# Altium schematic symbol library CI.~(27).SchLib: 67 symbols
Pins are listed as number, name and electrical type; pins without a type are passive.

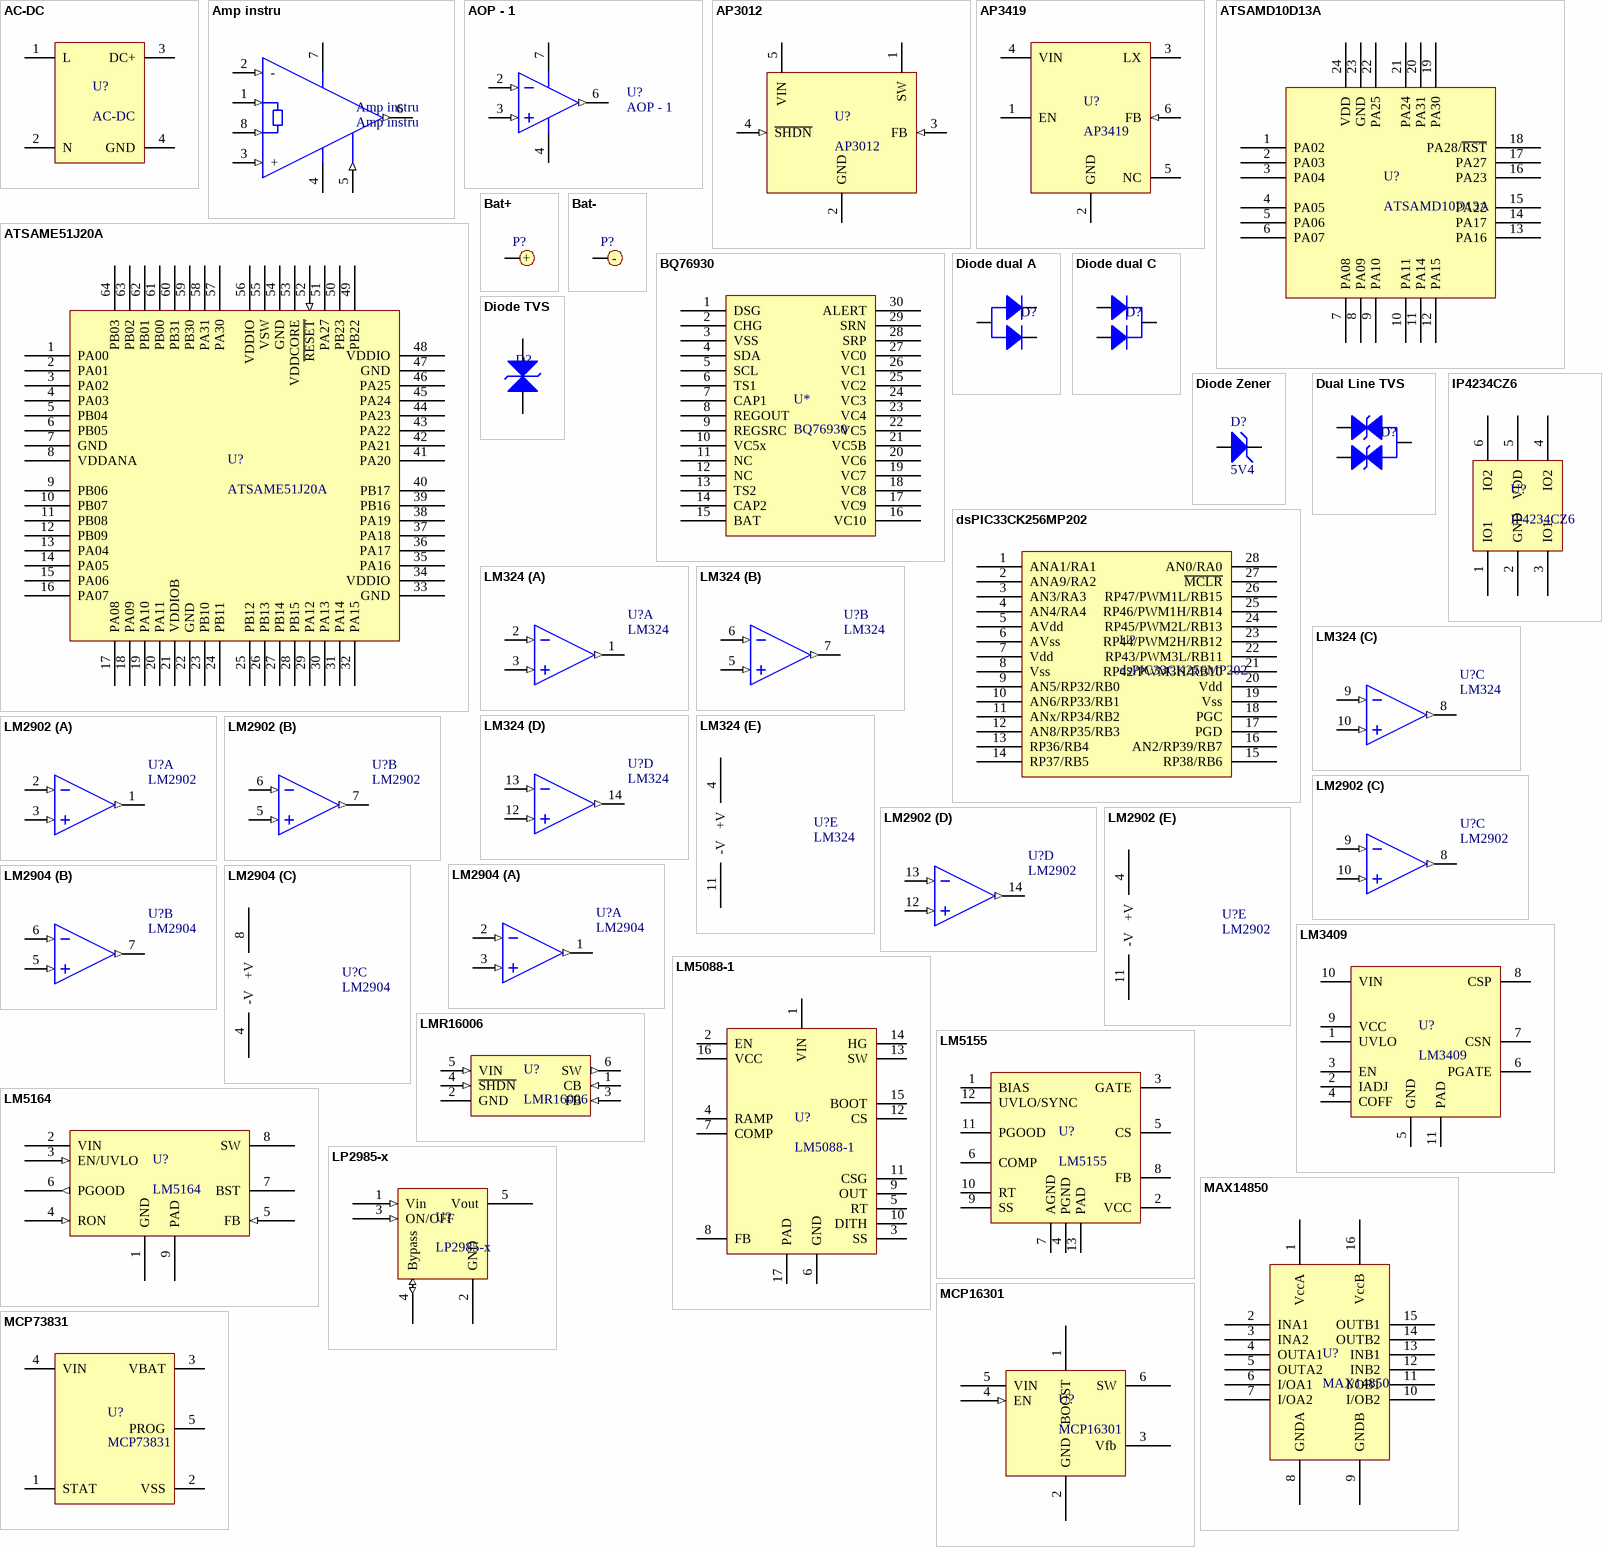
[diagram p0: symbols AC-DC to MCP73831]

## AC-DC
designator U?
footprint AC-DC 3W
footprint AC-DC 1W; pin to pad 1>4 2>3 3>2 4>1
pins: 1 L, 2 N, 3 DC+, 4 GND

## Amp instru
designator Amp instru
Instrument Amplifier
pins: 1 (in), 2 - (in), 3 + (in), 4 V- (power), 5 Ref (in), 6 OUT (out), 7 V+ (power), 8 (in)

## AOP - 1
designator U?
footprint SOIC-8 (8-Pin Plastic Narrow Body Small Outline Integrated Circuit 1.27 mm Pitch, IPC Medium Density)
pins: 2 IN- (in), 3 IN+ (in), 4 V- (power), 6 OUT (out), 7 V+ (power)

## AP3012
designator U?
1.5MHz boost DC-DC converter, current mode
footprint SOT-23-5 (SOT-23 5pins)
pins: 1 SW, 2 GND (power), 3 FB (in), 4 ~{SHDN} (in), 5 VIN (power)

## AP3419
designator U?
2A buck DC-DC converter
footprint TSOP2-6 (TSOP, 6-Leads, Body 2,90x1,60mm, Pitch 0,95mm, IPC Medium Density)
pins: 1 EN, 2 GND (power), 3 LX (power), 4 VIN (power), 5 NC (hiz), 6 FB (in)

## ATSAMD10D13A
designator U?
footprint SMSC QFN-24 4x4MM (QFN, 24-Leads, Body 4.1x4.1mm (max), Pitch 0.50mm, IPC Medium Density)
pins: 1 PA02, 2 PA03, 3 PA04, 4 PA05, 5 PA06, 6 PA07, 7 PA08, 8 PA09, 9 PA10, 10 PA11, 11 PA14, 12 PA15, 13 PA16, 14 PA17, 15 PA22, 16 PA23, 17 PA27, 18 PA28/~{RST}, 19 PA30, 20 PA31, 21 PA24, 22 PA25, 23 GND (power), 24 VDD (power)

## ATSAME51J20A
designator U?
footprint TQFP-64N (TSQFP, 64-Leads, Body 10,00x10,00mm, Pitch 0,50mm, IPC Medium Density)
pins: 1 PA00, 2 PA01, 3 PA02, 4 PA03, 5 PB04, 6 PB05, 7 GND (power), 8 VDDANA (power), 9 PB06, 10 PB07, 11 PB08, 12 PB09, 13 PA04, 14 PA05, 15 PA06, 16 PA07, 17 PA08, 18 PA09, 19 PA10, 20 PA11, 21 VDDIOB (power), 22 GND (power), 23 PB10, 24 PB11, 25 PB12, 26 PB13, 27 PB14, 28 PB15, 29 PA12, 30 PA13, 31 PA14, 32 PA15, 33 GND (power), 34 VDDIO (power), 35 PA16, 36 PA17, 37 PA18, 38 PA19, 39 PB16, 40 PB17, 41 PA20, 42 PA21, 43 PA22, 44 PA23, 45 PA24, 46 PA25, 47 GND (power), 48 VDDIO (power), 49 PB22, 50 PB23, 51 PA27, 52 ~{RESET} (in), 53 VDDCORE (power), 54 GND (power), 55 VSW (power), 56 VDDIO (power), 57 PA30, 58 PA31, 59 PB30, 60 PB31, 61 PB00, 62 PB01, 63 PB02, 64 PB03

## Bat+
designator P?  (value not drawn)
Battery contact +
footprint Keystone 2982 (Battery contact Keystone 2982)
pins: 1

## Bat-
designator P?  (value not drawn)
Battery contact -
footprint Keystone 2993 (Battery contact Keystone 2993)
pins: 1

## BQ76930
designator U*
footprint TSSOP-30
pins: 1 DSG, 2 CHG, 3 VSS, 4 SDA, 5 SCL, 6 TS1, 7 CAP1, 8 REGOUT, 9 REGSRC, 10 VC5x, 11 NC, 12 NC, 13 TS2, 14 CAP2, 15 BAT, 16 VC10, 17 VC9, 18 VC8, 19 VC7, 20 VC6, 21 VC5B, 22 VC5, 23 VC4, 24 VC3, 25 VC2, 26 VC1, 27 VC0, 28 SRP, 29 SRN, 30 ALERT

## Diode dual A
designator D?
Diode 2 common Anode
footprint DIODES SOT-23-3 (SOT23, 3-Leads, Body 2.90x2.40mm, Pitch 0.95mm, IPC Medium Density)
pins: 1 K1, 2 K2, 3 A

## Diode dual C
designator D?
Diode 2 common Cathode
footprint DIODES SOT-23-3 (SOT23, 3-Leads, Body 2.90x2.40mm, Pitch 0.95mm, IPC Medium Density)
pins: 1 A1, 2 A2, 3 K

## Diode TVS
designator D?  (value not drawn)
TVS diode
pins: A, K

## Diode Zener
designator D?, comment 5V4
Diode Zener
footprint DIODE-0.7 (Diode, Thru-Hole; 2 Leads; 0.7 in Pin Spacing)
simulation model ZENER (Diode)
signal-integrity model D Zener
pins: 1 A, 2 K

## dsPIC33CK256MP202
designator U?
footprint TI SSOP-28 DB (TSSOP, 28-Leads, Body 10.20x5.30mm, Pitch 0.65mm, IPC Medium Density)
pins: 1 ANA1/RA1, 2 ANA9/RA2, 3 AN3/RA3, 4 AN4/RA4, 5 AVdd (power), 6 AVss (power), 7 Vdd (power), 8 Vss (power), 9 AN5/RP32/RB0, 10 AN6/RP33/RB1, 11 ANx/RP34/RB2, 12 AN8/RP35/RB3, 13 RP36/RB4, 14 RP37/RB5, 15 RP38/RB6, 16 AN2/RP39/RB7, 17 PGD, 18 PGC, 19 Vss (power), 20 Vdd (power), 21 RP42/PWM3H/RB10, 22 RP43/PWM3L/RB11, 23 RP44/PWM2H/RB12, 24 RP45/PWM2L/RB13, 25 RP46/PWM1H/RB14, 26 RP47/PWM1L/RB15, 27 ~{MCLR}, 28 AN0/RA0

## Dual Line TVS
designator D?
Dual Line TVS
footprint DIODES SOT-23-3 (SOT23, 3-Leads, Body 2.90x2.40mm, Pitch 0.95mm, IPC Medium Density)
pins: 1, 2, 3

## IP4234CZ6
designator U?
Single USB 2.0 ESD protection to IEC 61000-4-2 level 4
footprint VISHAY TSOP-6 MO-193C (SOT23, 6-Leads, Body 3.03x2.84mm, Pitch 0.95mm, IPC Medium Density)
pins: 1 IO1, 2 GND (power), 3 IO1, 4 IO2, 5 VDD (power), 6 IO2

## LM324
designator U?
ow power quad operational amplifiers
footprint SOIC-14 (14-Pin Plastic Narrow Body Small Outline Integrated Circuit 1.27 mm Pitch, IPC Medium Density)
part A pins: 1 OUT (out), 2 IN- (in), 3 IN+ (in)
part B pins: 5 IN+ (in), 6 IN- (in), 7 OUT (out)
part C pins: 8 OUT (out), 9 IN- (in), 10 IN+ (in)
part D pins: 12 IN+ (in), 13 IN- (in), 14 OUT (out)
part E pins: 4 +V (power), 11 -V (power)

## LM2902
designator U?
Low-power quad operational amplifiers
footprint Atmel SO-14 14S1 (SOIC, 14-Leads, Body 8.65x3.90mm, Pitch 1.27mm, IPC Medium Density)
part A pins: 1 OUT (out), 2 IN- (in), 3 IN+ (in)
part B pins: 5 IN+ (in), 6 IN- (in), 7 OUT (out)
part C pins: 8 OUT (out), 9 IN- (in), 10 IN+ (in)
part D pins: 12 IN+ (in), 13 IN- (in), 14 OUT (out)
part E pins: 4 +V (power), 11 -V (power)

## LM2904
designator U?
Low-power dual operational amplifiers
footprint DIODES SO-8 (SOIC, 8-Leads, Body 4.90x3.90mm, Pitch 1.27mm, IPC Medium Density)
part A pins: 1 OUT (out), 2 IN- (in), 3 IN+ (in)
part B pins: 5 IN+ (in), 6 IN- (in), 7 OUT (out)
part C pins: 4 -V (power), 8 +V (power)

## LM3409
designator U?
P-FET Buck Controller for High-Power LED Drivers
footprint TI MSOP-10 DGQ (TSSOP, 10-Leads, Body 3x3mm, Pitch 0.5mm, Thermal Pad 1.88x1.57mm, IPC Medium Density)
pins: 1 UVLO, 2 IADJ (power), 3 EN, 4 COFF, 5 GND (power), 6 PGATE, 7 CSN, 8 CSP, 9 VCC, 10 VIN (power), 11 PAD (power)

## LM5088-1
designator U?
Wide Input Range Non-Synchronous Buck Controller
footprint TI MSOP-10 DGQ (TSSOP, 10-Leads, Body 3x3mm, Pitch 0.5mm, Thermal Pad 1.88x1.57mm, IPC Medium Density)
pins: 1 VIN (power), 2 EN, 3 SS, 4 RAMP, 5 RT, 6 GND (power), 7 COMP, 8 FB, 9 OUT, 10 DITH, 11 CSG, 12 CS, 13 SW, 14 HG, 15 BOOT, 16 VCC (power), 17 PAD (power)

## LM5155
designator U?
2.2-MHz Wide Input Nonsynchronous Boost, SEPIC, Flyback Controller
footprint TI MSOP-10 DGQ (TSSOP, 10-Leads, Body 3x3mm, Pitch 0.5mm, Thermal Pad 1.88x1.57mm, IPC Medium Density)
pins: 1 BIAS, 2 VCC (power), 3 GATE, 4 PGND, 5 CS, 6 COMP, 7 AGND (power), 8 FB, 9 SS, 10 RT, 11 PGOOD, 12 UVLO/SYNC, 13 PAD (power)

## LM5164
designator U?
100-V Input, 1-A synchronous buck DC/DC converter with ultra-low IQ
footprint R-PDSO-G8 (SOIC, 8-Leads, Body 4,90x3,90mm, Pitch 1,27mm, Thermal Pad 3,10x2,40mm, IPC Medium Density)
pins: 1 GND (power), 2 VIN (power), 3 EN/UVLO (in), 4 RON (in), 5 FB (in), 6 PGOOD (out), 7 BST (power), 8 SW (power), 9 PAD (power)

## LMR16006
designator U?
4 to 60V in, 0.5V out buck converter
footprint DPSO-6
pins: 1 CB (in), 2 GND (power), 3 FB (in), 4 ~{SHDN} (in), 5 VIN (in), 6 SW (out)

## LP2985-x
designator U?
150mA, Low-Noise, 350mVdrop max, LDO voltage regulator
footprint SOT-23-5 (SOT-23 5pins)
pins: 1 Vin (in), 2 GND (power), 3 ON/OFF (in), 4 Bypass (io), 5 Vout (power)

## MAX14850
designator U?
Six-Channel Digital Isolator
footprint SI LABS SOIC-16 WIDE (SOIC, 16-Leads, Body 10.30x7.50mm, Pitch 1.27mm, IPC Medium Density)
pins: 1 VccA (power), 2 INA1, 3 INA2, 4 OUTA1, 5 OUTA2, 6 I/OA1, 7 I/OA2, 8 GNDA (power), 9 GNDB (power), 10 I/OB2, 11 I/OB1, 12 INB2, 13 INB1, 14 OUTB2, 15 OUTB1, 16 VccB (power)

## MCP16301
designator U?
High-Voltage Input Integrated Switch Step-Down Regulator
footprint TI SOT-23-6 DDC (SOT23, 6-Leads, Body 2.90x2.80mm, Pitch 0.95mm, IPC Medium Density)
pins: 1 BOOST, 2 GND (power), 3 Vfb, 4 EN (in), 5 VIN (power), 6 SW

## MCP73831
designator U?
Miniature Single-Cell, Fully Integrated Li-Ion,Li-Polymer Charge Management Controllers
footprint MICROCHIP SOT-23-5 OT (SOT23, 5-Leads, Body 2.90x2.70mm, Pitch 0.95mm, IPC Medium Density)
pins: 1 STAT, 2 VSS (power), 3 VBAT (power), 4 VIN (power), 5 PROG

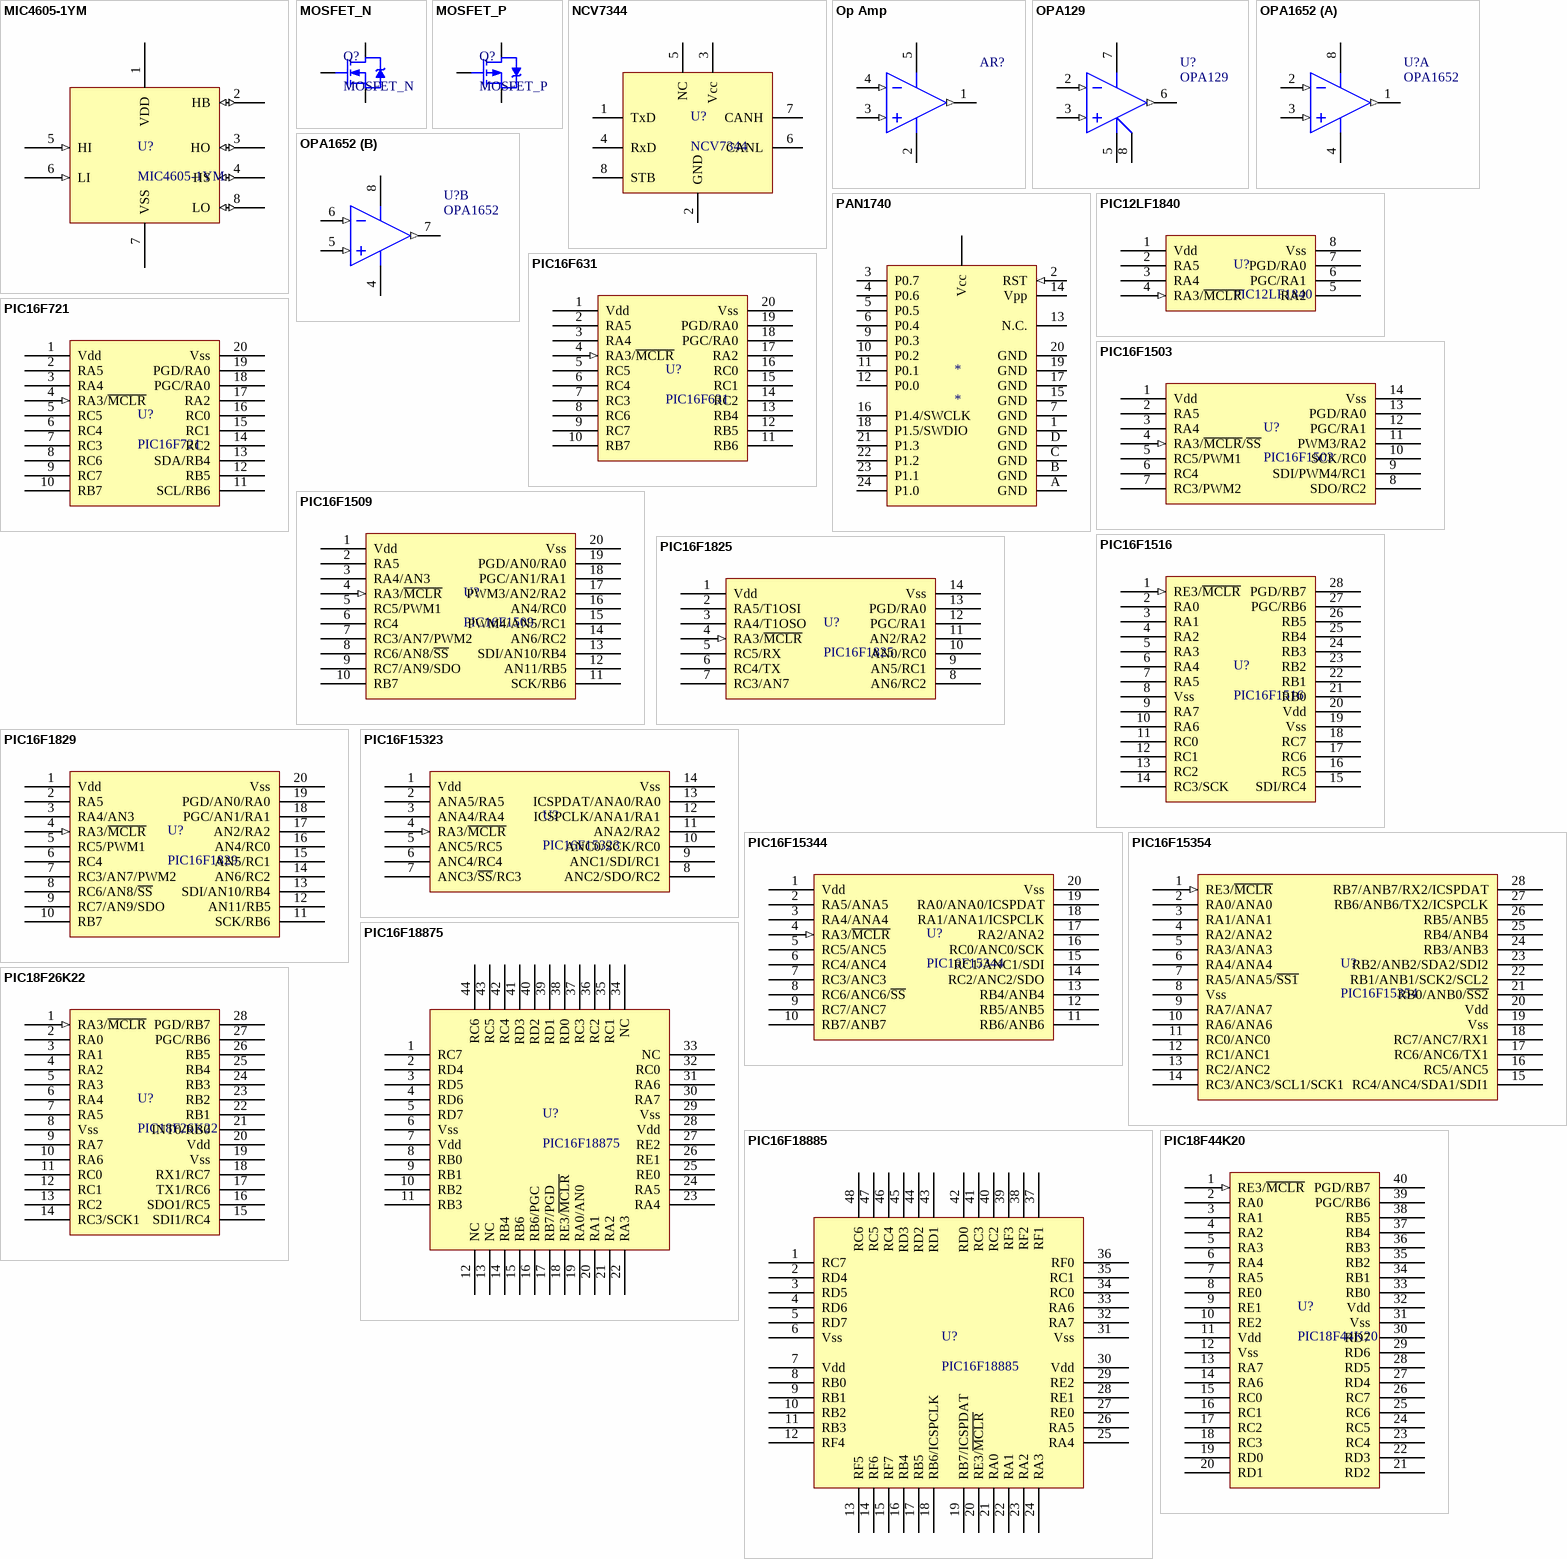
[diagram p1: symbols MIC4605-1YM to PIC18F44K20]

## MIC4605-1YM
designator U?
85V Half-Bridge MOSFET Driver with Adaptive Dead Time  and Shoot-Through Protection
footprint SOIC-8 (8-Pin Plastic Narrow Body Small Outline Integrated Circuit 1.27 mm Pitch, IPC Medium Density)
pins: 1 VDD (power), 2 HB (io), 3 HO (io), 4 HS (io), 5 HI (in), 6 LI (in), 7 VSS (power), 8 LO (io)

## MOSFET_N
designator Q?
pins: 1 G, 2 S, 3 D

## MOSFET_P
designator Q?
pins: 1 G, 2 S, 3 D

## NCV7344
designator U?
High Speed Low PowerCAN, CAN FD Transceiver
footprint ON SEMI SO-8 (SOIC, 8-Leads, Body 4.90x3.90mm, Pitch 1.27mm, IPC Medium Density)
pins: 1 TxD, 2 GND (power), 3 Vcc (power), 4 RxD, 5 NC (power), 6 CANL, 7 CANH, 8 STB

## Op Amp
designator AR?
FET Operational Amplifier
footprint H-08A (Can; 8 Leads; Pin Circle Dia. 5.08 mm; Lead Dia. 0.53 mm (max))
simulation model AD645A (Spice Subcircuit)
pins: 1 OUT (out), 2 V- (power), 3 IN+ (in), 4 IN- (in), 5 V+ (power)

## OPA129
designator U?
FET Operational Amplifier
footprint H-08A (Can; 8 Leads; Pin Circle Dia. 5.08 mm; Lead Dia. 0.53 mm (max))
simulation model AD645A (Spice Subcircuit)
pins: 2 IN- (in), 3 IN+ (in), 5 V- (power), 6 OUT (out), 7 V+ (power), 8 V- (power)

## OPA1652
designator U?
Low Noise and Distortion, General-Purpose, FET-Input Audio Op Amps
footprint SOIC-8 (8-Pin Plastic Narrow Body Small Outline Integrated Circuit 1.27 mm Pitch, IPC Medium Density)
pins on every part: 4 V- (power), 8 V+ (power)
part A pins: 1 OUT (out), 2 IN- (in), 3 IN+ (in)
part B pins: 5 IN+ (in), 6 IN- (in), 7 OUT (out)

## PAN1740
designator *
pins: 1 GND (power), 2 RST (in), 3 P0.7, 4 P0.6, 5 P0.5, 6 P0.4, 7 GND (power), 8 Vcc (power), 9 P0.3, 10 P0.2, 11 P0.1, 12 P0.0, 13 N.C., 14 Vpp (power), 15 GND (power), 16 P1.4/SWCLK, 17 GND (power), 18 P1.5/SWDIO, 19 GND (power), 20 GND (power), 21 P1.3, 22 P1.2, 23 P1.1, 24 P1.0, A GND (power), B GND (power), C GND (power), D GND (power)

## PIC12LF1840
designator U?
pins: 1 Vdd (power), 2 RA5, 3 RA4, 4 RA3/~{MCLR} (in), 5 RA2, 6 PGC/RA1, 7 PGD/RA0, 8 Vss (power)

## PIC16F631
designator U?
pins: 1 Vdd (power), 2 RA5, 3 RA4, 4 RA3/~{MCLR} (in), 5 RC5, 6 RC4, 7 RC3, 8 RC6, 9 RC7, 10 RB7, 11 RB6, 12 RB5, 13 RB4, 14 RC2, 15 RC1, 16 RC0, 17 RA2, 18 PGC/RA0, 19 PGD/RA0, 20 Vss (power)

## PIC16F721
designator U?
pins: 1 Vdd (power), 2 RA5, 3 RA4, 4 RA3/~{MCLR} (in), 5 RC5, 6 RC4, 7 RC3, 8 RC6, 9 RC7, 10 RB7, 11 SCL/RB6, 12 RB5, 13 SDA/RB4, 14 RC2, 15 RC1, 16 RC0, 17 RA2, 18 PGC/RA0, 19 PGD/RA0, 20 Vss (power)

## PIC16F1503
designator U?
pins: 1 Vdd (power), 2 RA5, 3 RA4, 4 RA3/~{MCLR}/~{SS} (in), 5 RC5/PWM1, 6 RC4, 7 RC3/PWM2, 8 SDO/RC2, 9 SDI/PWM4/RC1, 10 SCK/RC0, 11 PWM3/RA2, 12 PGC/RA1, 13 PGD/RA0, 14 Vss (power)

## PIC16F1509
designator U?
pins: 1 Vdd (power), 2 RA5, 3 RA4/AN3, 4 RA3/~{MCLR} (in), 5 RC5/PWM1, 6 RC4, 7 RC3/AN7/PWM2, 8 RC6/AN8/~{SS}, 9 RC7/AN9/SDO, 10 RB7, 11 SCK/RB6, 12 AN11/RB5, 13 SDI/AN10/RB4, 14 AN6/RC2, 15 PWM4/AN5/RC1, 16 AN4/RC0, 17 PWM3/AN2/RA2, 18 PGC/AN1/RA1, 19 PGD/AN0/RA0, 20 Vss (power)

## PIC16F1516
designator U?
pins: 1 RE3/~{MCLR} (in), 2 RA0, 3 RA1, 4 RA2, 5 RA3, 6 RA4, 7 RA5, 8 Vss (power), 9 RA7, 10 RA6, 11 RC0, 12 RC1, 13 RC2, 14 RC3/SCK, 15 SDI/RC4, 16 RC5, 17 RC6, 18 RC7, 19 Vss (power), 20 Vdd (power), 21 RB0, 22 RB1, 23 RB2, 24 RB3, 25 RB4, 26 RB5, 27 PGC/RB6, 28 PGD/RB7

## PIC16F1825
designator U?
footprint TSSOP-14
footprint SOIC-14 (14-Pin Plastic Narrow Body Small Outline Integrated Circuit 1.27 mm Pitch, IPC Medium Density)
pins: 1 Vdd (power), 2 RA5/T1OSI, 3 RA4/T1OSO, 4 RA3/~{MCLR} (in), 5 RC5/RX, 6 RC4/TX, 7 RC3/AN7, 8 AN6/RC2, 9 AN5/RC1, 10 AN0/RC0, 11 AN2/RA2, 12 PGC/RA1, 13 PGD/RA0, 14 Vss (power)

## PIC16F1829
designator U?
pins: 1 Vdd (power), 2 RA5, 3 RA4/AN3, 4 RA3/~{MCLR} (in), 5 RC5/PWM1, 6 RC4, 7 RC3/AN7/PWM2, 8 RC6/AN8/~{SS}, 9 RC7/AN9/SDO, 10 RB7, 11 SCK/RB6, 12 AN11/RB5, 13 SDI/AN10/RB4, 14 AN6/RC2, 15 AN5/RC1, 16 AN4/RC0, 17 AN2/RA2, 18 PGC/AN1/RA1, 19 PGD/AN0/RA0, 20 Vss (power)

## PIC16F15323
designator U?
footprint MICROCHIP TSSOP-14 4.4MM BODY (TSSOP, 14-Leads, Body 5.00x4.40mm, Pitch 0.65mm, IPC Medium Density)
pins: 1 Vdd (power), 2 ANA5/RA5, 3 ANA4/RA4, 4 RA3/~{MCLR} (in), 5 ANC5/RC5, 6 ANC4/RC4, 7 ANC3/~{SS}/RC3, 8 ANC2/SDO/RC2, 9 ANC1/SDI/RC1, 10 ANC0/SCK/RC0, 11 ANA2/RA2, 12 ICSPCLK/ANA1/RA1, 13 ICSPDAT/ANA0/RA0, 14 Vss (power)

## PIC16F15344
designator U?
footprint MICROCHIP TSSOP-20 4.4MM BODY (TSSOP, 20-Leads, Body 6.50x4.40mm, Pitch 0.65mm, IPC Medium Density)
pins: 1 Vdd (power), 2 RA5/ANA5, 3 RA4/ANA4, 4 RA3/~{MCLR} (in), 5 RC5/ANC5, 6 RC4/ANC4, 7 RC3/ANC3, 8 RC6/ANC6/~{SS}, 9 RC7/ANC7, 10 RB7/ANB7, 11 RB6/ANB6, 12 RB5/ANB5, 13 RB4/ANB4, 14 RC2/ANC2/SDO (power), 15 RC1/ANC1/SDI, 16 RC0/ANC0/SCK, 17 RA2/ANA2, 18 RA1/ANA1/ICSPCLK, 19 RA0/ANA0/ICSPDAT, 20 Vss

## PIC16F15354
designator U?
footprint SSOP_28
pins: 1 RE3/~{MCLR} (in), 2 RA0/ANA0, 3 RA1/ANA1, 4 RA2/ANA2, 5 RA3/ANA3, 6 RA4/ANA4, 7 RA5/ANA5/~{SS1}, 8 Vss (power), 9 RA7/ANA7, 10 RA6/ANA6, 11 RC0/ANC0, 12 RC1/ANC1, 13 RC2/ANC2, 14 RC3/ANC3/SCL1/SCK1, 15 RC4/ANC4/SDA1/SDI1, 16 RC5/ANC5, 17 RC6/ANC6/TX1, 18 RC7/ANC7/RX1, 19 Vss (power), 20 Vdd (power), 21 RB0/ANB0/~{SS2}, 22 RB1/ANB1/SCK2/SCL2, 23 RB2/ANB2/SDA2/SDI2, 24 RB3/ANB3, 25 RB4/ANB4, 26 RB5/ANB5, 27 RB6/ANB6/TX2/ICSPCLK, 28 RB7/ANB7/RX2/ICSPDAT

## PIC16F18875
designator U?
pins: 1 RC7, 2 RD4, 3 RD5, 4 RD6, 5 RD7, 6 Vss (power), 7 Vdd (power), 8 RB0, 9 RB1, 10 RB2, 11 RB3, 12 NC, 13 NC, 14 RB4, 15 RB6, 16 RB6/PGC, 17 RB7/PGD, 18 RE3/~{MCLR}, 19 RA0/AN0, 20 RA1, 21 RA2, 22 RA3, 23 RA4, 24 RA5, 25 RE0, 26 RE1, 27 RE2, 28 Vdd (power), 29 Vss (power), 30 RA7, 31 RA6, 32 RC0, 33 NC, 34 NC, 35 RC1, 36 RC2, 37 RC3, 38 RD0, 39 RD1, 40 RD2, 41 RD3, 42 RC4, 43 RC5, 44 RC6

## PIC16F18885
designator U?
footprint TQFP-48N (TSQFP, 48-Leads, Body 7,00x7,00mm, Pitch 0,50mm, IPC Medium Density)
pins: 1 RC7, 2 RD4, 3 RD5, 4 RD6, 5 RD7, 6 Vss (power), 7 Vdd (power), 8 RB0, 9 RB1, 10 RB2, 11 RB3, 12 RF4, 13 RF5, 14 RF6, 15 RF7, 16 RB4, 17 RB5, 18 RB6/ICSPCLK, 19 RB7/ICSPDAT, 20 RE3/~{MCLR}, 21 RA0, 22 RA1, 23 RA2, 24 RA3, 25 RA4, 26 RA5, 27 RE0, 28 RE1, 29 RE2, 30 Vdd (power), 31 Vss (power), 32 RA7, 33 RA6, 34 RC0, 35 RC1, 36 RF0, 37 RF1, 38 RF2, 39 RF3, 40 RC2, 41 RC3, 42 RD0, 43 RD1, 44 RD2, 45 RD3, 46 RC4, 47 RC5, 48 RC6

## PIC18F26K22
designator U?
pins: 1 RA3/~{MCLR} (in), 2 RA0, 3 RA1, 4 RA2, 5 RA3, 6 RA4, 7 RA5, 8 Vss (power), 9 RA7, 10 RA6, 11 RC0, 12 RC1, 13 RC2, 14 RC3/SCK1, 15 SDI1/RC4, 16 SDO1/RC5, 17 TX1/RC6, 18 RX1/RC7, 19 Vss (power), 20 Vdd (power), 21 INT0/RB0, 22 RB1, 23 RB2, 24 RB3, 25 RB4, 26 RB5, 27 PGC/RB6, 28 PGD/RB7

## PIC18F44K20
designator U?
pins: 1 RE3/~{MCLR} (in), 2 RA0, 3 RA1, 4 RA2, 5 RA3, 6 RA4, 7 RA5, 8 RE0, 9 RE1, 10 RE2, 11 Vdd (power), 12 Vss (power), 13 RA7, 14 RA6, 15 RC0, 16 RC1, 17 RC2, 18 RC3, 19 RD0, 20 RD1, 21 RD2, 22 RD3, 23 RC4, 24 RC5, 25 RC6, 26 RC7, 27 RD4, 28 RD5, 29 RD6, 30 RD7, 31 Vss (power), 32 Vdd (power), 33 RB0, 34 RB1, 35 RB2, 36 RB3, 37 RB4, 38 RB5, 39 PGC/RB6, 40 PGD/RB7

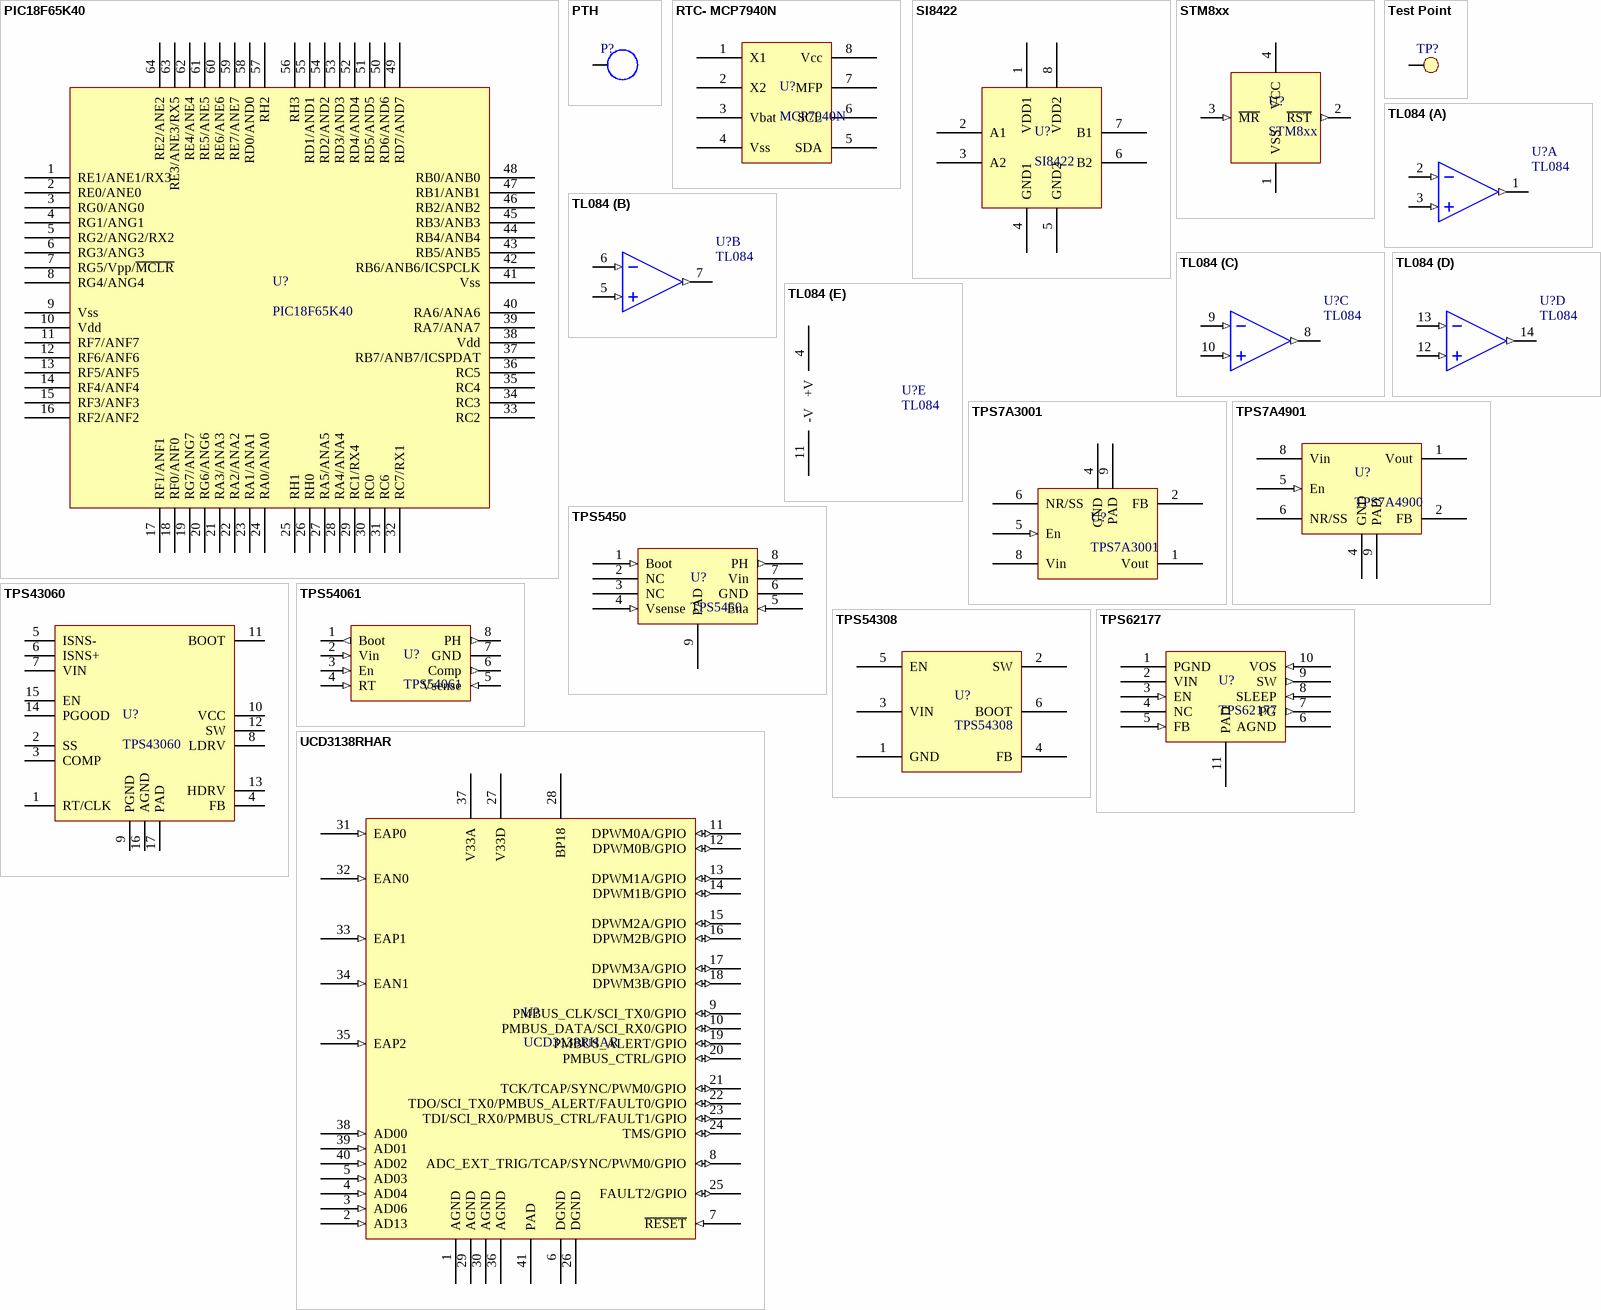
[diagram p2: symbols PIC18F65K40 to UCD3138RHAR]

## PIC18F65K40
designator U?
64-Pin, Low-Power, High-Performance Microcontrollers
footprint LQFP64 (LQFP, 64-Leads, Body 10,00x10,00mm, Pitch 0,50mm, IPC Medium Density)
pins: 1 RE1/ANE1/RX3, 2 RE0/ANE0, 3 RG0/ANG0, 4 RG1/ANG1, 5 RG2/ANG2/RX2, 6 RG3/ANG3, 7 RG5/Vpp/~{MCLR}, 8 RG4/ANG4, 9 Vss, 10 Vdd, 11 RF7/ANF7, 12 RF6/ANF6, 13 RF5/ANF5, 14 RF4/ANF4, 15 RF3/ANF3, 16 RF2/ANF2, 17 RF1/ANF1, 18 RF0/ANF0, 19 RG7/ANG7, 20 RG6/ANG6, 21 RA3/ANA3, 22 RA2/ANA2, 23 RA1/ANA1, 24 RA0/ANA0, 25 RH1, 26 RH0, 27 RA5/ANA5, 28 RA4/ANA4, 29 RC1/RX4, 30 RC0, 31 RC6, 32 RC7/RX1, 33 RC2, 34 RC3, 35 RC4, 36 RC5, 37 RB7/ANB7/ICSPDAT, 38 Vdd, 39 RA7/ANA7, 40 RA6/ANA6, 41 Vss, 42 RB6/ANB6/ICSPCLK, 43 RB5/ANB5, 44 RB4/ANB4, 45 RB3/ANB3, 46 RB2/ANB2, 47 RB1/ANB1, 48 RB0/ANB0, 49 RD7/AND7, 50 RD6/AND6, 51 RD5/AND5, 52 RD4/AND4, 53 RD3/AND3, 54 RD2/AND2, 55 RD1/AND1, 56 RH3, 57 RH2, 58 RD0/AND0, 59 RE7/ANE7, 60 RE6/ANE6, 61 RE5/ANE5, 62 RE4/ANE4, 63 RE3/ANE3/RX5, 64 RE2/ANE2

## PTH
designator P?  (value not drawn)
Plated Trough Hole for screew
footprint HOLE_4 (Hole for M4 screw)
pins: 1

## RTC- MCP7940N
designator U?, comment MCP7940N
pins: 1 X1, 2 X2, 3 Vbat, 4 Vss, 5 SDA, 6 SCL, 7 MFP, 8 Vcc

## SI8422
designator U?
Low-Power, Dual-Channel Digital Isolators
footprint ANALOG SO-8 R-8 (SOIC, 8-Leads, Body 4.90x3.90mm, Pitch 1.27mm, IPC Medium Density)
pins: 1 VDD1 (power), 2 A1, 3 A2, 4 GND1 (power), 5 GND2 (power), 6 B2, 7 B1, 8 VDD2 (power)

## STM8xx
designator U?
Voltage monitor
footprint SOT143-4
pins: 1 VSS (power), 2 ~{RST} (out), 3 ~{MR} (in), 4 VCC (power)

## Test Point
designator TP?  (value not drawn)
footprint Test Point
pins: 1

## TL084
designator U?
Quad operational amplifiers, 36V
footprint TSSOP-14
part A pins: 1 OUT (out), 2 IN- (in), 3 IN+ (in)
part B pins: 5 IN+ (in), 6 IN- (in), 7 OUT (out)
part C pins: 8 OUT (out), 9 IN- (in), 10 IN+ (in)
part D pins: 12 IN+ (in), 13 IN- (in), 14 OUT (out)
part E pins: 4 +V (power), 11 -V (power)

## TPS7A3001
designator U?
Ultra low noise positive adjustable LDO
footprint DGN8_PAD (MSOP-PowerPAD; 8 Leads; Pitch 0.65 mm)
simulation model TPS7A3001
pins: 1 Vout (power), 2 FB, 4 GND (power), 5 En (in), 6 NR/SS, 8 Vin (power), 9 PAD (power)

## TPS7A4901
designator U?, comment TPS7A4900
Ultra low noise positive adjustable LDO
footprint DGN8_PAD (MSOP-PowerPAD; 8 Leads; Pitch 0.65 mm)
simulation model TPS7A4901
pins: 1 Vout (power), 2 FB, 4 GND (power), 5 En (in), 6 NR/SS, 8 Vin (power), 9 PAD (power)

## TPS5450
designator U?
pins: 1 Boot (in), 2 NC (hiz), 3 NC (hiz), 4 Vsense (in), 5 Ena (in), 6 GND (power), 7 Vin (power), 8 PH (out), 9 PAD (power)

## TPS43060
designator U?
Low Quiescent Current Synchronous Boost  DC-DC Controller With Wide VIN Range
footprint TI WQFN-16 RGH (QFN, 16-Leads, Body 4.00x4.00mm, Pitch 0.50mm, Thermal Pad 2.60x2.60mm, IPC Medium Density)
pins: 1 RT/CLK, 2 SS, 3 COMP, 4 FB, 5 ISNS-, 6 ISNS+, 7 VIN (power), 8 LDRV, 9 PGND (power), 10 VCC, 11 BOOT, 12 SW, 13 HDRV, 14 PGOOD, 15 EN, 16 AGND (power), 17 PAD (power)

## TPS54061
designator U?
pins: 1 Boot (out), 2 Vin (in), 3 En (in), 4 RT (in), 5 Vsense (in), 6 Comp (out), 7 GND (power), 8 PH (out), 9 PAD (power) hidden to GND

## TPS54308
designator U?
4.5-V to 28-V Input, 3-A Output,  Synchronous 350-kHz FCCM Step-Down Converter in SOT23 Package
footprint TI SOT-23-6 DDC (SOT23, 6-Leads, Body 2.90x2.80mm, Pitch 0.95mm, IPC Medium Density)
pins: 1 GND (power), 2 SW, 3 VIN (power), 4 FB, 5 EN, 6 BOOT

## TPS62177
designator U?
3.3V 0.5A Buck converter
footprint WSON-10 (QFN10 + termal pad)
pins: 1 PGND (power), 2 VIN (power), 3 EN (in), 4 NC (hiz), 5 FB (in), 6 AGND (power), 7 PG (out), 8 SLEEP (in), 9 SW (out), 10 VOS (in), 11 PAD (power)

## UCD3138RHAR
designator U?
Highly Integrated Digital Controller for Isolated Power with 3 Feedback Loops and 8 DPWM Outputs, 40pins
footprint S-PVQFN-N40 (VQFN, 40-Leads, Body 6,00x6,00mm, Pitch 0,50mm, Thermal Pad 4,92x4,92mm, IPC Medium Density)
pins: 1 AGND (power), 2 AD13 (in), 3 AD06 (in), 4 AD04 (in), 5 AD03 (in), 6 DGND (power), 7 ~{RESET} (in), 8 ADC_EXT_TRIG/TCAP/SYNC/PWM0/GPIO (io), 9 PMBUS_CLK/SCI_TX0/GPIO (io), 10 PMBUS_DATA/SCI_RX0/GPIO (io), 11 DPWM0A/GPIO (io), 12 DPWM0B/GPIO (io), 13 DPWM1A/GPIO (io), 14 DPWM1B/GPIO (io), 15 DPWM2A/GPIO (io), 16 DPWM2B/GPIO (io), 17 DPWM3A/GPIO (io), 18 DPWM3B/GPIO (io), 19 PMBUS_ALERT/GPIO (io), 20 PMBUS_CTRL/GPIO (io), 21 TCK/TCAP/SYNC/PWM0/GPIO (io), 22 TDO/SCI_TX0/PMBUS_ALERT/FAULT0/GPIO (io), 23 TDI/SCI_RX0/PMBUS_CTRL/FAULT1/GPIO (io), 24 TMS/GPIO (io), 25 FAULT2/GPIO (io), 26 DGND (power), 27 V33D (power), 28 BP18 (power), 29 AGND (power), 30 AGND (power), 31 EAP0 (in), 32 EAN0 (in), 33 EAP1 (in), 34 EAN1 (in), 35 EAP2 (in), 36 AGND (power), 37 V33A (power), 38 AD00 (in), 39 AD01 (in), 40 AD02 (in), 41 PAD (power)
